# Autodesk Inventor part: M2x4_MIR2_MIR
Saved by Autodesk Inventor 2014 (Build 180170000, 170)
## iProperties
Created: 2015-05
Part Number: M2x4_MIR2_MIR
Material: 일반
Vendor: CBT Solutions
Document SubType Name: 모델링
Designer: Administrator
Appearance: 기본값
Company: 한국ATC센터
Author: KYOUNG IL JANG
Comments: 파생
d0: 1.000 ul
d0_1: 1.000 ul
d0_1_1: 1.000 ul
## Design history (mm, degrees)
derived "M2x4_MIR2.ipt"
feature "솔리드1::M2x4_MIR2.ipt"
tag "피쳐 태그1"
node "솔리드1"
other parameters: "d0" = 1, "d0_1" = 1, "d0_1_1" = 1
